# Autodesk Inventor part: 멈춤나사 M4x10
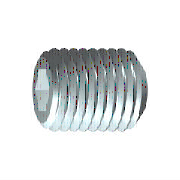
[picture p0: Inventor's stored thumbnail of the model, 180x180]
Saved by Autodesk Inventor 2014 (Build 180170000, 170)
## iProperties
Created: 2012-02
Part Number: 멈춤나사 M4x10
Material: 강철, 연강
Description: 6각 소켓 머리 없는 멈춤 나사
Document SubType Name: Modeling
Standard: KS B 1028
Designer: mduedu
Standards Organization: KS
Language: ko-KR
Size Designation: 납작점M4x10
Categories: <MemberInstance><Categories><Category DisplayName="조임쇠" InternalName="e4da775c-781d-43d5-af7c-5136215cf5a6" Mnemonic="FSTN"><Category DisplayName="볼트" InternalN
Density: 1 g/cm^3
Appearance: 강철
IsCustomPart: 1
Author: mduedu
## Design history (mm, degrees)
sketch "스케치1"
  geometry: L1 (0, 0)-(6.833, 0); L2 (10, 1.155)-(10, 2); L3 (10, 2)-(0, 2); L4 (10, 1.155)-(7.5, 1.155); L5 (7.5, 1.155)-(6.833, 0); L6 (0, -0.4)-(0, 2.4) reference; L7 (0, 2)-(0, 0)
  constraints: 13 end point, 3 parallel, 1 collinear, 1 perpendicular, 1 point on line
  dimensions: "d0" = 2.5 distance of L2.start L4.end (= INTI); "d1" = 60 deg angle of L5 L1; "d2" = 4 diameter of L3 L1 (= NND); "d3" = 2.3094 diameter of L4 L1 (= 1.1547 x SW); "d5" = 10 distance from line of L2 L3.end (= NLG)
revolve "본체" sketch "스케치1" stored, may be unused: angle "d6" = 90 deg
sketch "스케치2"
  geometry: L1 (-0.577, 1)-(0.577, 1); L2 (0.577, 1)-(1.155, 0); L3 (1.155, 0)-(0.577, -1); L4 (0.577, -1)-(-0.577, -1); L5 (-0.577, -1)-(-1.155, 0); L6 (-1.155, 0)-(-0.577, 1); A1 r 1.155 centre (0, 0) between (-0.577, 1) and (0.577, 1) reference; 2 further points
  constraints: 12 end point, 2 point on circle, 1 coincident, 1 horizontal, 11 other
extrude "슬롯" join sketch "스케치2" taper "d9" = 0 deg; stored distance "d21" = 10
workaxis "Work Axis1"
workplane "Work Plane1"
node "작업점1"
  node "작업축2"
body "Solid1"
chamfer "모따기1" distance "d7" = 0.42941 (= -0.5 x GD1 + 0.5 x NND); stored, may be unused: angle "d8" = 45 deg (= FAWI), second distance "d29" = 0.42941 (= -0.5 x GD1 + 0.5 x NND)
feature "스레드" dims "d11" = 10 (= NLG), "d12" = 0
chamfer "모따기2" distance "d13" = 0.42941 (= -0.5 x GD1 + 0.5 x NND); stored, may be unused: angle "d14" = 45 deg (= FAWI), second distance "d30" = 0.42941 (= -0.5 x GD1 + 0.5 x NND)
other parameters: "NND" = 4 [user parameter; used in 5 equation terms], "NLG" = 10 [user parameter; used in 2 equation terms], "INTI" = 2.5 [user parameter; used in 1 equation term], "FAWI" = 45 deg [user parameter; used in 2 equation terms], "SW" = 2 [user parameter; used in 2 equation terms], "GD1" = 3.14117 (= THREADDIA - 1.2269 x PTC) [user parameter; used in 4 equation terms], "d4" = 0, "FAWI1" = 45 deg [user parameter], "d15" = 0, "d31" = 0, "GUL" = 0.42941 (= 0.61345 x PTC) [user parameter], "SPD" = 2.5 [user parameter], "TPU" = 14.28571 (computed from PTC) [user parameter], "TOA" = 30 deg [user parameter], "THREADDIA" = 4 [user parameter; used in 1 equation term], "PTC" = 0.7 [user parameter; used in 4 equation terms], "GAL" = 0.42941 (= 0.61345 x PTC) [user parameter], "E0" = 2.31 (= 1.155 x SW) [user parameter]
